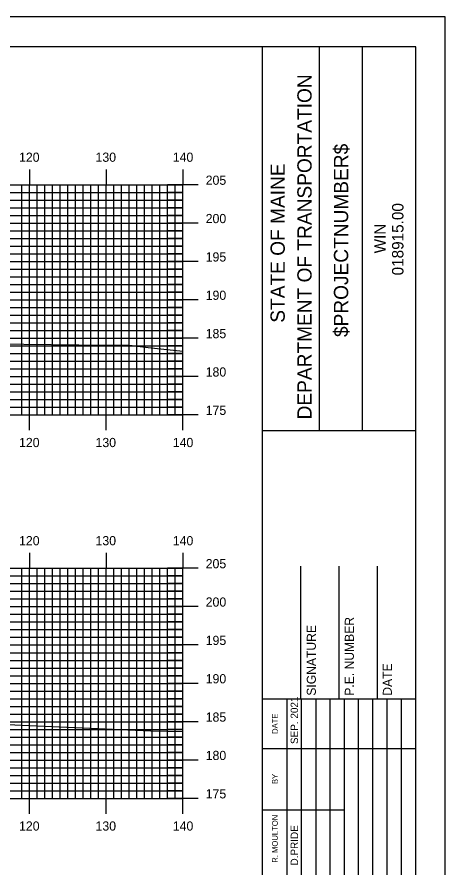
# Model space of a CAD drawing. Extents: x 1807832 to 1808175, y 442591 to 442811.
# Drawn here: x 1808116.2 to 1808172, y 442699.6 to 442810.5 of the extents above; entities that cross this region are included whole.
import ezdxf

# ---------------------------------------------------------------- set-up
doc = ezdxf.new("R2010")
doc.units = 0
for name, color, linetype in [('BORDER', 7, 'Continuous'), ('H_V ANNOTATION', 7, 'Continuous'), ('MAJOR', 7, 'Continuous'), ('MINOR', 7, 'Continuous'), ('PLOT BOUNDARY', 7, 'Continuous'), ('S_Roadway_Centerline', 7, 'Continuous')]:
    doc.layers.add(name, color=color, linetype=linetype)

msp = doc.modelspace()

# ---------------------------------------------------------------- linework, layer by layer
at = {"layer": 'BORDER'}
for p, q in [((1808148.18, 442596.67), (1808148.18, 442806.67)), ((1808155.64, 442756.66), (1808155.64, 442806.66)), ((1808161.23, 442756.66), (1808161.23, 442806.66)), ((1808148.19, 442756.65), (1808168.18, 442756.65)), ((1808153.18, 442721.67), (1808153.18, 442738.97)), ((1808158.18, 442721.67), (1808158.18, 442738.97)), ((1808163.18, 442721.67), (1808163.18, 442738.97)), ((1808148.18, 442721.67), (1808168.18, 442721.67))]:
    msp.add_line(p, q, dxfattribs=at)
msp.add_lwpolyline([(1807848.18, 442596.67), (1808168.18, 442596.67), (1808168.18, 442806.67), (1807848.18, 442806.67)], close=True, dxfattribs=at)
for points in [[(1808151.41, 442715.17), (1808151.41, 442721.67)], [(1808153.28, 442686.68), (1808153.28, 442721.67)], [(1808155.14, 442721.67), (1808155.14, 442686.68)], [(1808157.01, 442686.68), (1808157.01, 442721.67)], [(1808158.87, 442686.68), (1808158.87, 442721.67)], [(1808160.73, 442686.68), (1808160.73, 442721.67)], [(1808162.6, 442686.68), (1808162.6, 442721.67)], [(1808164.46, 442686.68), (1808164.46, 442721.67)], [(1808166.32, 442686.68), (1808166.32, 442721.67)], [(1808151.42, 442686.68), (1808151.42, 442720.26)], [(1808148.18, 442715.17), (1808168.18, 442715.17)], [(1808148.18, 442707.17), (1808151.42, 442707.17)], [(1808151.41, 442707.17), (1808158.87, 442707.17)]]:
    msp.add_lwpolyline(points, dxfattribs=at)
at = {"layer": 'MAJOR'}
for p, q in [((1808117.78, 442790.67), (1808117.78, 442788.67)), ((1808127.78, 442790.67), (1808127.78, 442788.67)), ((1808137.78, 442790.67), (1808137.78, 442788.67)), ((1807857.78, 442788.67), (1808137.78, 442788.67)), ((1807857.78, 442788.67), (1808137.78, 442788.67)), ((1808117.78, 442758.67), (1808117.78, 442788.67)), ((1808127.78, 442758.67), (1808127.78, 442788.67)), ((1808139.79, 442788.67), (1808135.78, 442788.67)), ((1808137.78, 442758.67), (1808137.78, 442788.67)), ((1808137.78, 442758.67), (1808137.78, 442788.67)), ((1807857.78, 442783.67), (1808137.78, 442783.67)), ((1808139.79, 442783.67), (1808135.78, 442783.67)), ((1807857.78, 442778.67), (1808137.78, 442778.67)), ((1808139.79, 442778.67), (1808135.78, 442778.67)), ((1807857.78, 442773.67), (1808137.78, 442773.67)), ((1808139.79, 442773.67), (1808135.78, 442773.67)), ((1807857.78, 442768.67), (1808137.78, 442768.67)), ((1808139.79, 442768.67), (1808135.78, 442768.67)), ((1807857.78, 442763.67), (1808137.78, 442763.67)), ((1808139.79, 442763.67), (1808135.78, 442763.67)), ((1807857.78, 442758.67), (1808137.78, 442758.67)), ((1807857.78, 442758.67), (1808137.78, 442758.67)), ((1808117.78, 442756.66), (1808117.78, 442758.67)), ((1808127.78, 442756.66), (1808127.78, 442758.67)), ((1808139.79, 442758.67), (1808135.78, 442758.67)), ((1808137.78, 442756.66), (1808137.78, 442758.67)), ((1808117.78, 442740.67), (1808117.78, 442738.67)), ((1808127.78, 442740.67), (1808127.78, 442738.67)), ((1808137.78, 442740.67), (1808137.78, 442738.67)), ((1807857.78, 442738.67), (1808137.78, 442738.67)), ((1807857.78, 442738.67), (1808137.78, 442738.67)), ((1808117.78, 442708.67), (1808117.78, 442738.67)), ((1808127.78, 442708.67), (1808127.78, 442738.67)), ((1808139.79, 442738.67), (1808135.78, 442738.67)), ((1808137.78, 442708.67), (1808137.78, 442738.67)), ((1808137.78, 442708.67), (1808137.78, 442738.67)), ((1807857.78, 442733.67), (1808137.78, 442733.67)), ((1808139.79, 442733.67), (1808135.78, 442733.67)), ((1807857.78, 442728.67), (1808137.78, 442728.67)), ((1808139.79, 442728.67), (1808135.78, 442728.67)), ((1807857.78, 442723.67), (1808137.78, 442723.67)), ((1808139.79, 442723.67), (1808135.78, 442723.67)), ((1807857.78, 442718.67), (1808137.78, 442718.67)), ((1808139.79, 442718.67), (1808135.78, 442718.67)), ((1807857.78, 442713.67), (1808137.78, 442713.67)), ((1808139.79, 442713.67), (1808135.78, 442713.67)), ((1807857.78, 442708.67), (1808137.78, 442708.67)), ((1807857.78, 442708.67), (1808137.78, 442708.67)), ((1808117.78, 442706.66), (1808117.78, 442708.67)), ((1808127.78, 442706.66), (1808127.78, 442708.67)), ((1808139.79, 442708.67), (1808135.78, 442708.67)), ((1808137.78, 442706.66), (1808137.78, 442708.67))]:
    msp.add_line(p, q, dxfattribs=at)
at = {"layer": 'MINOR'}
for p, q in [((1808116.78, 442758.67), (1808116.78, 442788.67)), ((1808118.78, 442758.67), (1808118.78, 442788.67)), ((1808119.78, 442758.67), (1808119.78, 442788.67)), ((1808120.78, 442758.67), (1808120.78, 442788.67)), ((1808121.78, 442758.67), (1808121.78, 442788.67)), ((1808122.78, 442758.67), (1808122.78, 442788.67)), ((1808123.78, 442758.67), (1808123.78, 442788.67)), ((1808124.78, 442758.67), (1808124.78, 442788.67)), ((1808125.78, 442758.67), (1808125.78, 442788.67)), ((1808126.78, 442758.67), (1808126.78, 442788.67)), ((1808128.78, 442758.67), (1808128.78, 442788.67)), ((1808129.78, 442758.67), (1808129.78, 442788.67)), ((1808130.78, 442758.67), (1808130.78, 442788.67)), ((1808131.78, 442758.67), (1808131.78, 442788.67)), ((1808132.78, 442758.67), (1808132.78, 442788.67)), ((1808133.78, 442758.67), (1808133.78, 442788.67)), ((1808134.78, 442758.67), (1808134.78, 442788.67)), ((1808135.78, 442758.67), (1808135.78, 442788.67)), ((1808136.78, 442758.67), (1808136.78, 442788.67)), ((1807857.78, 442787.67), (1808137.78, 442787.67)), ((1808137.78, 442787.67), (1808135.78, 442787.67)), ((1807857.78, 442786.67), (1808137.78, 442786.67)), ((1808137.78, 442786.67), (1808135.78, 442786.67)), ((1807857.78, 442785.67), (1808137.78, 442785.67)), ((1808137.78, 442785.67), (1808135.78, 442785.67)), ((1807857.78, 442784.67), (1808137.78, 442784.67)), ((1808137.78, 442784.67), (1808135.78, 442784.67)), ((1807857.78, 442782.67), (1808137.78, 442782.67)), ((1807857.78, 442781.67), (1808137.78, 442781.67)), ((1808137.78, 442782.67), (1808135.78, 442782.67)), ((1808137.78, 442781.67), (1808135.78, 442781.67)), ((1807857.78, 442780.67), (1808137.78, 442780.67)), ((1808137.78, 442780.67), (1808135.78, 442780.67)), ((1807857.78, 442779.67), (1808137.78, 442779.67)), ((1808137.78, 442779.67), (1808135.78, 442779.67)), ((1807857.78, 442777.67), (1808137.78, 442777.67)), ((1808137.78, 442777.67), (1808135.78, 442777.67)), ((1807857.78, 442776.67), (1808137.78, 442776.67)), ((1808137.78, 442776.67), (1808135.78, 442776.67)), ((1807857.78, 442775.67), (1808137.78, 442775.67)), ((1808137.78, 442775.67), (1808135.78, 442775.67)), ((1807857.78, 442774.67), (1808137.78, 442774.67)), ((1808137.78, 442774.67), (1808135.78, 442774.67)), ((1807857.78, 442772.67), (1808137.78, 442772.67)), ((1808137.78, 442772.67), (1808135.78, 442772.67)), ((1807857.78, 442771.67), (1808137.78, 442771.67)), ((1807857.78, 442770.67), (1808137.78, 442770.67)), ((1808137.78, 442771.67), (1808135.78, 442771.67)), ((1808137.78, 442770.67), (1808135.78, 442770.67)), ((1807857.78, 442769.67), (1808137.78, 442769.67)), ((1808137.78, 442769.67), (1808135.78, 442769.67)), ((1807857.78, 442767.67), (1808137.78, 442767.67)), ((1808137.78, 442767.67), (1808135.78, 442767.67)), ((1807857.78, 442766.67), (1808137.78, 442766.67)), ((1808137.78, 442766.67), (1808135.78, 442766.67)), ((1807857.78, 442765.67), (1808137.78, 442765.67)), ((1808137.78, 442765.67), (1808135.78, 442765.67)), ((1807857.78, 442764.67), (1808137.78, 442764.67)), ((1808137.78, 442764.67), (1808135.78, 442764.67)), ((1807857.78, 442762.67), (1808137.78, 442762.67)), ((1808137.78, 442762.67), (1808135.78, 442762.67)), ((1807857.78, 442761.67), (1808137.78, 442761.67)), ((1807857.78, 442760.67), (1808137.78, 442760.67)), ((1808137.78, 442761.67), (1808135.78, 442761.67)), ((1808137.78, 442760.67), (1808135.78, 442760.67)), ((1807857.78, 442759.67), (1808137.78, 442759.67)), ((1808137.78, 442759.67), (1808135.78, 442759.67)), ((1808116.78, 442708.67), (1808116.78, 442738.67)), ((1808118.78, 442708.67), (1808118.78, 442738.67)), ((1808119.78, 442708.67), (1808119.78, 442738.67)), ((1808120.78, 442708.67), (1808120.78, 442738.67)), ((1808121.78, 442708.67), (1808121.78, 442738.67)), ((1808122.78, 442708.67), (1808122.78, 442738.67)), ((1808123.78, 442708.67), (1808123.78, 442738.67)), ((1808124.78, 442708.67), (1808124.78, 442738.67)), ((1808125.78, 442708.67), (1808125.78, 442738.67)), ((1808126.78, 442708.67), (1808126.78, 442738.67)), ((1808128.78, 442708.67), (1808128.78, 442738.67)), ((1808129.78, 442708.67), (1808129.78, 442738.67)), ((1808130.78, 442708.67), (1808130.78, 442738.67)), ((1808131.78, 442708.67), (1808131.78, 442738.67)), ((1808132.78, 442708.67), (1808132.78, 442738.67)), ((1808133.78, 442708.67), (1808133.78, 442738.67)), ((1808134.78, 442708.67), (1808134.78, 442738.67)), ((1808135.78, 442708.67), (1808135.78, 442738.67)), ((1808136.78, 442708.67), (1808136.78, 442738.67)), ((1807857.78, 442737.67), (1808137.78, 442737.67)), ((1808137.78, 442737.67), (1808135.78, 442737.67)), ((1807857.78, 442736.67), (1808137.78, 442736.67)), ((1808137.78, 442736.67), (1808135.78, 442736.67)), ((1807857.78, 442735.67), (1808137.78, 442735.67)), ((1808137.78, 442735.67), (1808135.78, 442735.67)), ((1807857.78, 442734.67), (1808137.78, 442734.67)), ((1808137.78, 442734.67), (1808135.78, 442734.67)), ((1807857.78, 442732.67), (1808137.78, 442732.67)), ((1808137.78, 442732.67), (1808135.78, 442732.67)), ((1807857.78, 442731.67), (1808137.78, 442731.67)), ((1807857.78, 442730.67), (1808137.78, 442730.67)), ((1808137.78, 442731.67), (1808135.78, 442731.67)), ((1808137.78, 442730.67), (1808135.78, 442730.67)), ((1807857.78, 442729.67), (1808137.78, 442729.67)), ((1808137.78, 442729.67), (1808135.78, 442729.67)), ((1807857.78, 442727.67), (1808137.78, 442727.67)), ((1808137.78, 442727.67), (1808135.78, 442727.67)), ((1807857.78, 442726.67), (1808137.78, 442726.67)), ((1808137.78, 442726.67), (1808135.78, 442726.67)), ((1807857.78, 442725.67), (1808137.78, 442725.67)), ((1808137.78, 442725.67), (1808135.78, 442725.67)), ((1807857.78, 442724.67), (1808137.78, 442724.67)), ((1808137.78, 442724.67), (1808135.78, 442724.67)), ((1807857.78, 442722.67), (1808137.78, 442722.67)), ((1808137.78, 442722.67), (1808135.78, 442722.67)), ((1807857.78, 442721.67), (1808137.78, 442721.67)), ((1807857.78, 442720.67), (1808137.78, 442720.67)), ((1808137.78, 442721.67), (1808135.78, 442721.67)), ((1808137.78, 442720.67), (1808135.78, 442720.67)), ((1807857.78, 442719.67), (1808137.78, 442719.67)), ((1808137.78, 442719.67), (1808135.78, 442719.67)), ((1807857.78, 442717.67), (1808137.78, 442717.67)), ((1808137.78, 442717.67), (1808135.78, 442717.67)), ((1807857.78, 442716.67), (1808137.78, 442716.67)), ((1808137.78, 442716.67), (1808135.78, 442716.67)), ((1807857.78, 442715.67), (1808137.78, 442715.67)), ((1808137.78, 442715.67), (1808135.78, 442715.67)), ((1807857.78, 442714.67), (1808137.78, 442714.67)), ((1808137.78, 442714.67), (1808135.78, 442714.67)), ((1807857.78, 442712.67), (1808137.78, 442712.67)), ((1808137.78, 442712.67), (1808135.78, 442712.67)), ((1807857.78, 442711.67), (1808137.78, 442711.67)), ((1807857.78, 442710.67), (1808137.78, 442710.67)), ((1808137.78, 442711.67), (1808135.78, 442711.67)), ((1808137.78, 442710.67), (1808135.78, 442710.67)), ((1807857.78, 442709.67), (1808137.78, 442709.67)), ((1808137.78, 442709.67), (1808135.78, 442709.67))]:
    msp.add_line(p, q, dxfattribs=at)
at = {"layer": 'PLOT BOUNDARY'}
msp.add_lwpolyline([(1807832, 442590.55), (1808172, 442590.55), (1808172, 442810.55), (1807832, 442810.55)], close=True, dxfattribs=at)
at = {"layer": 'S_Roadway_Centerline'}
for points in [[(1808050.25, 442769.82), (1808061.12, 442769.48), (1808070.84, 442769.1), (1808084.68, 442768.93), (1808092.02, 442768.79), (1808100.26, 442768.45), (1808113.43, 442767.92), (1808127.8, 442767.78), (1808130.82, 442767.75), (1808133.28, 442767.44), (1808137.78, 442766.96)], [(1808048.45, 442720.04), (1808059.94, 442719.83), (1808068.47, 442719.68), (1808070.71, 442719.59), (1808081.96, 442718.88), (1808090.97, 442718.68), (1808097.44, 442718.59), (1808105.54, 442718.53), (1808112.95, 442718.38), (1808121.67, 442717.98), (1808133.63, 442717.5), (1808137.78, 442717.41)]]:
    msp.add_lwpolyline(points, dxfattribs=at)

# ---------------------------------------------------------------- texts
at = {"layer": 'BORDER'}
for s, height, p in [('DEPARTMENT OF TRANSPORTATION', 1.8635, (1808154.6, 442758.08)), ('$PROJECTNUMBER$', 1.8635, (1808159.37, 442768.82)), ('STATE OF MAINE', 1.8635, (1808151.1, 442770.69)), ('018915.00', 1.491, (1808166.58, 442776.86)), ('WIN', 1.491, (1808164.26, 442779.73)), ('P.E. NUMBER', 1.1811, (1808160.11, 442722.06)), ('SIGNATURE', 1.181, (1808155.15, 442722.06)), ('DATE', 1.181, (1808165.07, 442722.06)), ('SEP. 2021', 0.969, (1808152.83, 442715.76)), ('DATE', 0.743, (1808150.19, 442717.08)), ('BY', 0.743, (1808150.19, 442710.54)), ('R. MOULTON', 0.745, (1808150.19, 442700.28)), ('D.PRIDE', 0.969, (1808152.83, 442699.92))]:
    msp.add_text(s, height=height, rotation=90, dxfattribs=at).set_placement(p)
at = {"layer": 'H_V ANNOTATION'}
for s, p in [('120', (1808116.43, 442791.67)), ('130', (1808126.41, 442791.67)), ('140', (1808136.49, 442791.67)), ('205', (1808140.78, 442788.67)), ('200', (1808140.78, 442783.67)), ('195', (1808140.78, 442778.67)), ('190', (1808140.78, 442773.67)), ('185', (1808140.78, 442768.67)), ('180', (1808140.78, 442763.67)), ('175', (1808140.78, 442758.67)), ('120', (1808116.43, 442754.47)), ('130', (1808126.41, 442754.47)), ('140', (1808136.49, 442754.47)), ('120', (1808116.43, 442741.67)), ('130', (1808126.41, 442741.67)), ('140', (1808136.49, 442741.67)), ('205', (1808140.78, 442738.67)), ('200', (1808140.78, 442733.67)), ('195', (1808140.78, 442728.67)), ('190', (1808140.78, 442723.67)), ('185', (1808140.78, 442718.67)), ('180', (1808140.78, 442713.67)), ('175', (1808140.78, 442708.67)), ('120', (1808116.43, 442704.47)), ('130', (1808126.41, 442704.47)), ('140', (1808136.49, 442704.47))]:
    msp.add_text(s, height=1.2, dxfattribs=at).set_placement(p)

doc.saveas('drawing.dxf')
